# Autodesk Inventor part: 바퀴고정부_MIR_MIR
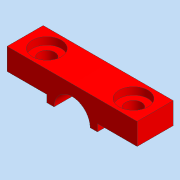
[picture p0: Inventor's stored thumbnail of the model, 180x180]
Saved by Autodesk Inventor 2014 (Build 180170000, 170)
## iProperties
Created: 2015-05
Part Number: 바퀴고정부_MIR_MIR
Material: 일반
Vendor: CBT Solutions
Document SubType Name: 모델링
Designer: Administrator
Appearance: 기본값
Company: 한국ATC센터
Author: KYOUNG IL JANG
Comments: 파생
d0: 1.000 ul
d0_1: 1.000 ul
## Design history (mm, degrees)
derived "바퀴고정부_MIR.ipt"
feature "솔리드1::바퀴고정부_MIR.ipt"
tag "피쳐 태그1"
node "솔리드1"
other parameters: "d0" = 1, "d0_1" = 1
